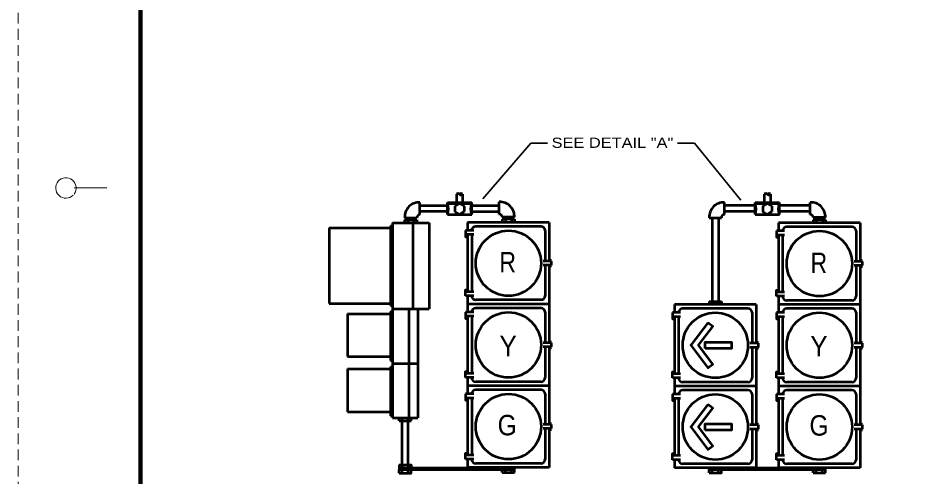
# Model space of a CAD drawing. Extents: x -295 to 385, y -102 to 338.
# Drawn here: x -295.3 to -75.4, y 114.2 to 226.3 of the extents above; entities that cross this region are included whole.
import ezdxf
from ezdxf.enums import TextEntityAlignment as Align

# ---------------------------------------------------------------- set-up
doc = ezdxf.new("R2010")
doc.units = 0
doc.header["$LTSCALE"] = 0.88
doc.linetypes.add('MEDIUM_DASHED', pattern=[4.5, 3, -1.5])
doc.layers.add('1', color=7, linetype='Continuous', lineweight=53)
doc.layers.add('61', color=7, linetype='Continuous', lineweight=35)

msp = doc.modelspace()

# ---------------------------------------------------------------- linework, layer by layer
at = {"layer": '1', "linetype": 'MEDIUM_DASHED', "lineweight": 13}
msp.add_line((-295.2093, 338.4444), (-295.2693, -101.5956), dxfattribs=at)
at = {"layer": '1', "lineweight": 35}
for p, q in [((-169.6052, 195.6138), (-181.359, 182.0472)), ((-169.6052, 195.6138), (-165.4462, 195.6138)), ((-133.6202, 195.6138), (-129.4613, 195.6138)), ((-129.4613, 195.6138), (-118.0689, 181.6855))]:
    msp.add_line(p, q, dxfattribs=at)
at = {"layer": '1'}
for p, q in [((-187.7792, 183.1532), (-187.7792, 181.1532)), ((-186.2792, 183.1532), (-186.2792, 181.1532)), ((-112.3568, 183.1532), (-112.3568, 181.1532)), ((-110.8568, 183.1532), (-110.8568, 181.1532)), ((-196.7419, 178.1532), (-196.7419, 181.1532)), ((-196.7419, 180.4117), (-190.0292, 180.4117)), ((-190.0292, 181.1532), (-184.0292, 181.1532)), ((-190.0292, 180.9032), (-184.0292, 180.9032)), ((-187.0292, 180.9032), (-188.1542, 180.2283)), ((-187.0292, 180.9032), (-185.9042, 180.2283)), ((-184.0292, 178.1532), (-184.0292, 181.1532)), ((-184.0292, 180.4117), (-177.3165, 180.4117)), ((-177.3165, 178.2563), (-177.3165, 181.2563)), ((-122.1068, 178.1532), (-122.1068, 181.1532)), ((-114.6068, 180.4032), (-122.1068, 180.4032)), ((-114.6068, 181.1532), (-108.6068, 181.1532)), ((-114.6068, 180.9032), (-108.6068, 180.9032)), ((-111.6068, 180.9032), (-112.7318, 180.2283)), ((-111.6068, 180.9032), (-110.4818, 180.2283)), ((-108.6068, 178.1532), (-108.6068, 181.1532)), ((-101.1068, 180.4032), (-108.6068, 180.4032)), ((-101.1068, 178.1617), (-101.1068, 181.1617)), ((-190.0292, 178.9032), (-196.7419, 178.9032)), ((-190.0292, 178.1532), (-184.0292, 178.1532)), ((-188.1542, 180.2283), (-188.1542, 178.8282)), ((-188.1542, 178.8282), (-187.0292, 178.1532)), ((-185.9042, 178.9282), (-187.0292, 178.1532)), ((-185.9042, 180.2283), (-185.9042, 178.9282)), ((-184.0292, 178.9117), (-177.3165, 178.9117)), ((-114.6068, 178.9032), (-122.1068, 178.9032)), ((-114.6068, 178.1532), (-108.6068, 178.1532)), ((-112.7318, 180.2283), (-112.7318, 178.8282)), ((-112.7318, 178.8282), (-111.6068, 178.1532)), ((-110.4818, 178.9282), (-111.6068, 178.1532)), ((-110.4818, 180.2283), (-110.4818, 178.9282)), ((-101.1068, 178.9032), (-108.6068, 178.9032)), ((-203.4919, 176.1532), (-203.4919, 128.4032)), ((-203.4919, 176.1532), (-194.4919, 176.1532)), ((-200.4919, 177.4032), (-197.4919, 177.4032)), ((-200.4919, 176.9032), (-200.4919, 176.1532)), ((-200.4919, 176.9032), (-197.4919, 176.9032)), ((-199.7419, 177.4032), (-199.7419, 176.1532)), ((-198.4919, 175.9032), (-198.4919, 155.3233)), ((-198.2419, 177.4032), (-198.2419, 176.1532)), ((-197.4919, 176.9032), (-197.4919, 176.1532)), ((-194.4919, 176.1532), (-194.4919, 155.0733)), ((-165.0665, 176.2563), (-185.0665, 176.2563)), ((-185.0665, 176.2563), (-185.0665, 174.2563)), ((-173.5665, 177.5063), (-176.5665, 177.5063)), ((-176.5665, 177.0063), (-176.5665, 176.2563)), ((-173.5665, 177.0063), (-176.5665, 177.0063)), ((-175.8165, 177.5063), (-175.8165, 176.2563)), ((-174.3165, 177.5063), (-174.3165, 176.2563)), ((-173.5665, 177.0063), (-173.5665, 176.2563)), ((-165.0665, 176.2563), (-165.0665, 166.7563)), ((-125.8568, 177.4032), (-122.8568, 177.4032)), ((-125.1068, 177.4032), (-125.1068, 156.1617)), ((-123.6068, 177.4032), (-123.6068, 156.1617)), ((-88.8568, 176.1617), (-108.8568, 176.1617)), ((-108.8568, 176.1617), (-108.8568, 174.1617)), ((-97.3568, 177.4117), (-100.3568, 177.4117)), ((-100.3568, 176.9117), (-100.3568, 176.1617)), ((-97.3568, 176.9117), (-100.3568, 176.9117)), ((-99.6068, 177.4117), (-99.6068, 176.1617)), ((-98.1068, 177.4117), (-98.1068, 176.1617)), ((-97.3568, 176.9117), (-97.3568, 176.1617)), ((-88.8568, 176.1617), (-88.8568, 166.6617)), ((-218.9919, 174.9032), (-203.9919, 174.9032)), ((-218.9919, 174.9032), (-218.9919, 156.4032)), ((-203.9919, 175.4032), (-203.4919, 175.4032)), ((-203.9919, 175.4032), (-203.9919, 155.9032)), ((-183.5665, 174.2563), (-185.5665, 174.2563)), ((-167.0665, 175.2563), (-183.0665, 175.2563)), ((-166.0665, 174.2563), (-166.0665, 166.7563)), ((-107.3568, 174.1617), (-109.3568, 174.1617)), ((-90.8568, 175.1617), (-106.8568, 175.1617)), ((-89.8568, 174.1617), (-89.8568, 166.6617)), ((-183.5665, 173.2563), (-185.5665, 173.2563)), ((-185.0665, 173.2563), (-185.0665, 159.2563)), ((-184.0665, 173.2563), (-184.0665, 159.2563)), ((-107.3568, 173.1617), (-109.3568, 173.1617)), ((-108.8568, 173.1617), (-108.8568, 159.1617)), ((-107.8568, 173.1617), (-107.8568, 159.1617)), ((-164.8165, 167.2563), (-164.8165, 166.7563)), ((-88.6068, 167.1617), (-88.6068, 166.6617)), ((-164.5665, 166.7563), (-166.5665, 166.7563)), ((-164.5665, 165.7563), (-166.5665, 165.7563)), ((-166.0665, 165.7563), (-166.0665, 158.2563)), ((-165.0665, 165.7563), (-165.0665, 156.2563)), ((-164.8165, 165.7563), (-164.8165, 165.2563)), ((-164.5665, 166.7563), (-164.5665, 165.7563)), ((-88.3568, 166.6617), (-90.3568, 166.6617)), ((-88.3568, 165.6617), (-90.3568, 165.6617)), ((-89.8568, 165.6617), (-89.8568, 158.1617)), ((-88.8568, 165.6617), (-88.8568, 156.1617)), ((-88.6068, 165.6617), (-88.6068, 165.1617)), ((-88.3568, 166.6617), (-88.3568, 165.6617)), ((-183.5665, 159.2563), (-185.5665, 159.2563)), ((-107.3568, 159.1617), (-109.3568, 159.1617)), ((-218.9919, 156.4032), (-203.9919, 156.4032)), ((-183.5665, 158.2563), (-185.5665, 158.2563)), ((-185.0665, 158.2563), (-185.0665, 156.2563)), ((-165.0665, 156.2563), (-185.0665, 156.2563)), ((-185.0665, 156.2563), (-185.0665, 154.2563)), ((-167.0665, 157.2563), (-183.0665, 157.2563)), ((-165.0665, 156.2563), (-165.0665, 146.7563)), ((-114.3568, 156.1617), (-134.3568, 156.1617)), ((-134.3568, 156.1617), (-134.3568, 154.1617)), ((-125.8568, 156.9117), (-125.8568, 156.1617)), ((-125.8568, 156.9117), (-122.8568, 156.9117)), ((-122.8568, 156.9117), (-122.8568, 156.1617)), ((-114.3568, 156.1617), (-114.3568, 146.6617)), ((-107.3568, 158.1617), (-109.3568, 158.1617)), ((-108.8568, 158.1617), (-108.8568, 156.1617)), ((-88.8568, 156.1617), (-108.8568, 156.1617)), ((-108.8568, 156.1617), (-108.8568, 154.1617)), ((-90.8568, 157.1617), (-106.8568, 157.1617)), ((-88.8568, 156.1617), (-88.8568, 146.6617)), ((-203.9919, 155.9032), (-203.4919, 155.9032)), ((-203.9919, 154.4032), (-203.9919, 142.4032)), ((-203.9919, 154.4032), (-203.4919, 154.4032)), ((-203.4919, 155.0733), (-194.4919, 155.0733)), ((-199.4919, 154.8233), (-199.4919, 128.6532)), ((-197.2419, 155.0733), (-197.2419, 128.4032)), ((-183.5665, 154.2563), (-185.5665, 154.2563)), ((-167.0665, 155.2563), (-183.0665, 155.2563)), ((-166.0665, 154.2563), (-166.0665, 146.7563)), ((-132.8568, 154.1617), (-134.8568, 154.1617)), ((-116.3568, 155.1617), (-132.3568, 155.1617)), ((-115.3568, 154.1617), (-115.3568, 146.6617)), ((-107.3568, 154.1617), (-109.3568, 154.1617)), ((-90.8568, 155.1617), (-106.8568, 155.1617)), ((-89.8568, 154.1617), (-89.8568, 146.6617)), ((-214.4919, 153.9032), (-203.9919, 153.9032)), ((-214.4919, 153.9032), (-214.4919, 143.4032)), ((-183.5665, 153.2563), (-185.5665, 153.2563)), ((-185.0665, 153.2563), (-185.0665, 139.2563)), ((-184.0665, 153.2563), (-184.0665, 139.2563)), ((-132.8568, 153.1617), (-134.8568, 153.1617)), ((-134.3568, 153.1617), (-134.3568, 139.1617)), ((-133.3568, 153.1617), (-133.3568, 139.1617)), ((-107.3568, 153.1617), (-109.3568, 153.1617)), ((-108.8568, 153.1617), (-108.8568, 139.1617)), ((-107.8568, 153.1617), (-107.8568, 139.1617)), ((-164.5665, 146.7563), (-166.5665, 146.7563)), ((-164.5665, 145.7563), (-166.5665, 145.7563)), ((-166.0665, 145.7563), (-166.0665, 138.2563)), ((-165.0665, 145.7563), (-165.0665, 136.2563)), ((-164.8165, 147.2563), (-164.8165, 146.7563)), ((-164.8165, 145.7563), (-164.8165, 145.2563)), ((-164.5665, 146.7563), (-164.5665, 145.7563)), ((-113.8568, 146.6617), (-115.8568, 146.6617)), ((-113.8568, 145.6617), (-115.8568, 145.6617)), ((-115.3568, 145.6617), (-115.3568, 138.1617)), ((-114.3568, 145.6617), (-114.3568, 136.1617)), ((-114.1068, 147.1617), (-114.1068, 146.6617)), ((-114.1068, 145.6617), (-114.1068, 145.1617)), ((-113.8568, 146.6617), (-113.8568, 145.6617)), ((-88.3568, 146.6617), (-90.3568, 146.6617)), ((-88.3568, 145.6617), (-90.3568, 145.6617)), ((-89.8568, 145.6617), (-89.8568, 138.1617)), ((-88.8568, 145.6617), (-88.8568, 136.1617)), ((-88.6068, 147.1617), (-88.6068, 146.6617)), ((-88.6068, 145.6617), (-88.6068, 145.1617)), ((-88.3568, 146.6617), (-88.3568, 145.6617)), ((-214.4919, 143.4032), (-203.9919, 143.4032)), ((-203.9919, 142.4032), (-203.4919, 142.4032)), ((-203.9919, 140.9032), (-203.9919, 128.9032)), ((-203.9919, 140.9032), (-203.4919, 140.9032)), ((-203.4919, 141.7332), (-197.2419, 141.7332)), ((-214.4919, 140.4032), (-203.9919, 140.4032)), ((-214.4919, 140.4032), (-214.4919, 129.9032)), ((-183.5665, 139.2563), (-185.5665, 139.2563)), ((-132.8568, 139.1617), (-134.8568, 139.1617)), ((-107.3568, 139.1617), (-109.3568, 139.1617)), ((-183.5665, 138.2563), (-185.5665, 138.2563)), ((-185.0665, 138.2563), (-185.0665, 136.2563)), ((-167.0665, 137.2563), (-183.0665, 137.2563)), ((-132.8568, 138.1617), (-134.8568, 138.1617)), ((-134.3568, 138.1617), (-134.3568, 136.1617)), ((-116.3568, 137.1617), (-132.3568, 137.1617)), ((-107.3568, 138.1617), (-109.3568, 138.1617)), ((-108.8568, 138.1617), (-108.8568, 136.1617)), ((-90.8568, 137.1617), (-106.8568, 137.1617)), ((-183.5665, 134.2563), (-185.5665, 134.2563)), ((-165.0665, 136.2563), (-185.0665, 136.2563)), ((-185.0665, 136.2563), (-185.0665, 134.2563)), ((-167.0665, 135.2563), (-183.0665, 135.2563)), ((-166.0665, 134.2563), (-166.0665, 126.7563)), ((-165.0665, 136.2563), (-165.0665, 126.7563)), ((-132.8568, 134.1617), (-134.8568, 134.1617)), ((-114.3568, 136.1617), (-134.3568, 136.1617)), ((-134.3568, 136.1617), (-134.3568, 134.1617)), ((-116.3568, 135.1617), (-132.3568, 135.1617)), ((-115.3568, 134.1617), (-115.3568, 126.6617)), ((-114.3568, 136.1617), (-114.3568, 126.6617)), ((-107.3568, 134.1617), (-109.3568, 134.1617)), ((-88.8568, 136.1617), (-108.8568, 136.1617)), ((-108.8568, 136.1617), (-108.8568, 134.1617)), ((-90.8568, 135.1617), (-106.8568, 135.1617)), ((-89.8568, 134.1617), (-89.8568, 126.6617)), ((-88.8568, 136.1617), (-88.8568, 126.6617)), ((-183.5665, 133.2563), (-185.5665, 133.2563)), ((-185.0665, 133.2563), (-185.0665, 119.2563)), ((-184.0665, 133.2563), (-184.0665, 119.2563)), ((-132.8568, 133.1617), (-134.8568, 133.1617)), ((-134.3568, 133.1617), (-134.3568, 119.1617)), ((-133.3568, 133.1617), (-133.3568, 119.1617)), ((-107.3568, 133.1617), (-109.3568, 133.1617)), ((-108.8568, 133.1617), (-108.8568, 119.1617)), ((-107.8568, 133.1617), (-107.8568, 119.1617)), ((-214.4919, 129.9032), (-203.9919, 129.9032)), ((-203.9919, 128.9032), (-203.4919, 128.9032)), ((-203.4919, 128.4032), (-197.2419, 128.4032)), ((-201.8669, 127.6579), (-201.8669, 128.4079)), ((-201.8669, 127.6579), (-198.8669, 127.6579)), ((-198.8669, 127.6579), (-198.8669, 128.4079)), ((-164.5665, 126.7563), (-166.5665, 126.7563)), ((-164.5665, 125.7563), (-166.5665, 125.7563)), ((-166.0665, 125.7563), (-166.0665, 118.2563)), ((-165.0665, 125.7563), (-165.0665, 116.2563)), ((-164.8165, 127.2563), (-164.8165, 126.7563)), ((-164.8165, 125.7563), (-164.8165, 125.2563)), ((-164.5665, 126.7563), (-164.5665, 125.7563)), ((-113.8568, 126.6617), (-115.8568, 126.6617)), ((-113.8568, 125.6617), (-115.8568, 125.6617)), ((-115.3568, 125.6617), (-115.3568, 118.1617)), ((-114.3568, 125.6617), (-114.3568, 116.1617)), ((-114.1068, 127.1617), (-114.1068, 126.6617)), ((-114.1068, 125.6617), (-114.1068, 125.1617)), ((-113.8568, 126.6617), (-113.8568, 125.6617)), ((-88.3568, 126.6617), (-90.3568, 126.6617)), ((-88.3568, 125.6617), (-90.3568, 125.6617)), ((-89.8568, 125.6617), (-89.8568, 118.1617)), ((-88.8568, 125.6617), (-88.8568, 116.1617)), ((-88.6068, 127.1617), (-88.6068, 126.6617)), ((-88.6068, 125.6617), (-88.6068, 125.1617)), ((-88.3568, 126.6617), (-88.3568, 125.6617)), ((-183.5665, 119.2563), (-185.5665, 119.2563)), ((-132.8568, 119.1617), (-134.8568, 119.1617)), ((-107.3568, 119.1617), (-109.3568, 119.1617)), ((-201.1169, 116.8874), (-201.1169, 116.0617)), ((-199.6169, 116.8874), (-199.6169, 116.0617)), ((-183.5665, 118.2563), (-185.5665, 118.2563)), ((-185.0665, 118.2563), (-185.0665, 116.2563)), ((-167.0665, 117.2563), (-183.0665, 117.2563)), ((-132.8568, 118.1617), (-134.8568, 118.1617)), ((-134.3568, 118.1617), (-134.3568, 116.1617)), ((-116.3568, 117.1617), (-132.3568, 117.1617)), ((-107.3568, 118.1617), (-109.3568, 118.1617)), ((-108.8568, 118.1617), (-108.8568, 116.1617)), ((-90.8568, 117.1617), (-106.8568, 117.1617)), ((-173.5665, 116.0617), (-201.8669, 116.0617)), ((-201.8669, 114.8369), (-201.8669, 115.6627)), ((-173.5665, 115.6617), (-201.8669, 115.6617)), ((-201.1169, 114.8369), (-201.1169, 115.6627)), ((-199.6169, 114.8369), (-199.6169, 115.6627)), ((-165.0665, 116.2563), (-185.0665, 116.2563)), ((-176.5665, 115.0063), (-176.5665, 115.7563)), ((-176.5665, 115.0063), (-173.5665, 115.0063)), ((-175.8165, 115.0063), (-175.8165, 115.7563)), ((-174.3165, 115.0063), (-174.3165, 115.7563)), ((-173.5665, 115.0063), (-173.5665, 116.2563)), ((-114.3568, 116.1617), (-134.3568, 116.1617)), ((-125.8568, 116.1617), (-125.8568, 115.7617)), ((-97.3568, 116.0617), (-125.8568, 116.0617)), ((-125.8568, 114.9369), (-125.8568, 115.7627)), ((-97.3568, 115.6617), (-125.8568, 115.6617)), ((-125.1068, 114.9369), (-125.1068, 115.6617)), ((-123.6068, 114.9369), (-123.6068, 115.6617)), ((-88.8568, 116.1617), (-108.8568, 116.1617)), ((-100.3568, 114.9117), (-100.3568, 115.6617)), ((-100.3568, 114.9117), (-97.3568, 114.9117)), ((-99.6068, 114.9117), (-99.6068, 115.6617)), ((-98.1068, 114.9117), (-98.1068, 115.6617)), ((-97.3568, 114.9117), (-97.3568, 116.1617))]:
    msp.add_line(p, q, dxfattribs=at)
for points in [[(-190.0292, 178.1532), (-190.0292, 180.9032), (-190.0292, 181.1532)], [(-114.6068, 178.1532), (-114.6068, 180.9032), (-114.6068, 181.1532)], [(-185.5665, 174.2563), (-185.5665, 172.7563), (-185.0665, 172.7563)], [(-109.3568, 174.1617), (-109.3568, 172.6617), (-108.8568, 172.6617)], [(-185.5665, 158.2563), (-185.5665, 159.7563), (-185.0665, 159.7563)], [(-109.3568, 158.1617), (-109.3568, 159.6617), (-108.8568, 159.6617)], [(-185.5665, 154.2563), (-185.5665, 152.7563), (-185.0665, 152.7563)], [(-134.8568, 154.1617), (-134.8568, 152.6617), (-134.3568, 152.6617)], [(-109.3568, 154.1617), (-109.3568, 152.6617), (-108.8568, 152.6617)], [(-185.5665, 138.2563), (-185.5665, 139.7563), (-185.0665, 139.7563)], [(-134.8568, 138.1617), (-134.8568, 139.6617), (-134.3568, 139.6617)], [(-109.3568, 138.1617), (-109.3568, 139.6617), (-108.8568, 139.6617)], [(-185.5665, 134.2563), (-185.5665, 132.7563), (-185.0665, 132.7563)], [(-134.8568, 134.1617), (-134.8568, 132.6617), (-134.3568, 132.6617)], [(-109.3568, 134.1617), (-109.3568, 132.6617), (-108.8568, 132.6617)], [(-201.1169, 116.8874), (-201.1169, 127.6579), (-201.1169, 128.4079)], [(-199.6169, 116.8874), (-199.6169, 127.6579), (-199.6169, 128.4079)], [(-185.5665, 118.2563), (-185.5665, 119.7563), (-185.0665, 119.7563)], [(-134.8568, 118.1617), (-134.8568, 119.6617), (-134.3568, 119.6617)], [(-109.3568, 118.1617), (-109.3568, 119.6617), (-108.8568, 119.6617)], [(-201.8669, 116.8874), (-198.8669, 116.8874), (-198.8669, 116.0617)], [(-201.8669, 116.8874), (-201.8669, 116.0617), (-201.8669, 115.6617)], [(-201.8669, 114.8369), (-198.8669, 114.8369), (-198.8669, 115.6627)], [(-125.8568, 114.9369), (-122.8568, 114.9369), (-122.8568, 115.6617)]]:
    msp.add_lwpolyline(points, dxfattribs=at)
for points in [[(-126.1591, 151.6617), (-130.3478, 146.1617), (-126.1555, 140.6617), (-124.9626, 141.571), (-128.4622, 146.1622), (-124.9658, 150.7529)], [(-126.8478, 145.4117), (-126.8478, 146.9117), (-120.3478, 146.9117), (-120.3478, 145.4117)], [(-126.1591, 131.6617), (-130.3478, 126.1617), (-126.1555, 120.6617), (-124.9626, 121.571), (-128.4622, 126.1622), (-124.9658, 130.7529)], [(-126.8478, 125.4117), (-126.8478, 126.9117), (-120.3478, 126.9117), (-120.3478, 125.4117)]]:
    msp.add_lwpolyline(points, close=True, dxfattribs=at)
for centre in [(-175.0575, 166.2583), (-98.8478, 166.1636), (-175.0575, 146.2583), (-124.3478, 146.1636), (-98.8478, 146.1636), (-175.0575, 126.2582), (-124.3478, 126.1636), (-98.8478, 126.1636)]:
    msp.add_circle(centre, 8, dxfattribs=at)
for centre, radius, start, end in [((-187.4042, 182.803), 0.5131, 43.04811, 136.95189), ((-186.6542, 182.803), 0.5131, 43.04811, 136.95189), ((-186.6542, 183.5), 0.5131, 223.04811, 316.95189), ((-111.9818, 182.803), 0.5131, 43.04811, 136.95189), ((-111.2318, 182.803), 0.5131, 43.04811, 136.95189), ((-111.2318, 183.5), 0.5131, 223.04811, 316.95189), ((-196.8998, 177.5611), 3.5956, 87.48391, 182.51609), ((-193.0811, 179.5282), 3.3474, 335.74702, 24.25298), ((-181.0079, 179.5282), 3.3474, 155.74702, 204.25298), ((-177.1587, 177.6642), 3.5956, 357.48391, 92.51609), ((-122.2647, 177.5611), 3.5956, 87.48391, 182.51609), ((-117.6588, 179.5282), 3.3474, 335.74702, 24.25298), ((-105.5855, 179.5282), 3.3474, 155.74702, 204.25298), ((-100.949, 177.5695), 3.5956, 357.48391, 92.51609), ((-196.7787, 177.44), 0.7142, 87.04875, 182.95125), ((-177.2797, 177.5431), 0.7142, 357.04875, 92.95125), ((-122.1436, 177.44), 0.7142, 87.04875, 182.95125), ((-101.0701, 177.4484), 0.7142, 357.04875, 92.95125), ((-183.0665, 174.2563), 1, 90, 180), ((-167.0665, 174.2563), 1, 0, 90), ((-106.8568, 174.1617), 1, 90, 180), ((-90.8568, 174.1617), 1, 0, 90), ((-183.0665, 158.2563), 1, 180, 270), ((-167.0665, 158.2563), 1, 270, 0), ((-106.8568, 158.1617), 1, 180, 270), ((-90.8568, 158.1617), 1, 270, 0), ((-183.0665, 154.2563), 1, 90, 180), ((-167.0665, 154.2563), 1, 0, 90), ((-132.3568, 154.1617), 1, 90, 180), ((-116.3568, 154.1617), 1, 0, 90), ((-106.8568, 154.1617), 1, 90, 180), ((-90.8568, 154.1617), 1, 0, 90), ((-183.0665, 138.2563), 1, 180, 270), ((-167.0665, 138.2563), 1, 270, 0), ((-132.3568, 138.1617), 1, 180, 270), ((-116.3568, 138.1617), 1, 270, 0), ((-106.8568, 138.1617), 1, 180, 270), ((-90.8568, 138.1617), 1, 270, 0), ((-183.0665, 134.2563), 1, 90, 180), ((-167.0665, 134.2563), 1, 0, 90), ((-132.3568, 134.1617), 1, 90, 180), ((-116.3568, 134.1617), 1, 0, 90), ((-106.8568, 134.1617), 1, 90, 180), ((-90.8568, 134.1617), 1, 0, 90), ((-183.0665, 118.2563), 1, 180, 270), ((-167.0665, 118.2563), 1, 270, 0), ((-132.3568, 118.1617), 1, 180, 270), ((-116.3568, 118.1617), 1, 270, 0), ((-106.8568, 118.1617), 1, 180, 270), ((-90.8568, 118.1617), 1, 270, 0)]:
    msp.add_arc(centre, radius, start, end, dxfattribs=at)
at = {"layer": '61', "lineweight": 13}
msp.add_line((-281.5093, 184.6844), (-273.5093, 184.6844), dxfattribs=at)
at = {"layer": '61', "lineweight": 158}
msp.add_lwpolyline([(373.8307, 328.4444), (-265.2093, 328.4444), (-265.2093, -91.5756)], dxfattribs=at)
at = {"layer": '61', "lineweight": 13}
msp.add_arc((-283.5116, 184.6857), 2.5, 323.13009, 315.37577, dxfattribs=at)

# ---------------------------------------------------------------- texts
at = {"layer": '1', "width": 1.2}
msp.add_text('SEE DETAIL "A"', height=2.5, dxfattribs=at).set_placement((-149.5625, 194.5033), align=Align.CENTER)
at = {"layer": '1'}
for s, width, p in [('R', 0.85, (-177.2967, 164.0118)), ('R', 0.85, (-101.0377, 163.8287)), ('Y', 0.95, (-177.2548, 143.5017)), ('Y', 0.95, (-101.074, 143.4461)), ('G', 0.9, (-177.7073, 124.1224)), ('G', 0.9, (-101.2781, 124.0547))]:
    msp.add_text(s, height=5, dxfattribs=dict(at, width=width)).set_placement(p)

doc.saveas('drawing.dxf')
